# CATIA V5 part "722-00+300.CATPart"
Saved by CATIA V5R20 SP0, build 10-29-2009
Part number: 722-00+300
Source: Unknown
Bounding box of the stored display mesh (mm): x -30 to 30, y -44.984 to 44.984, z 0 to 305
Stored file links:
  C:\Users\Utente\Desktop\IO LAVORO\3D X SITO CF\ULTIMI CATALOGO VERDE\3D files 722\722-00+300.CATPart
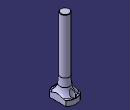
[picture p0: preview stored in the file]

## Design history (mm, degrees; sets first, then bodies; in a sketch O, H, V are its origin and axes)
Body1 (main body)
  Solid1 "PartBody": solid without history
